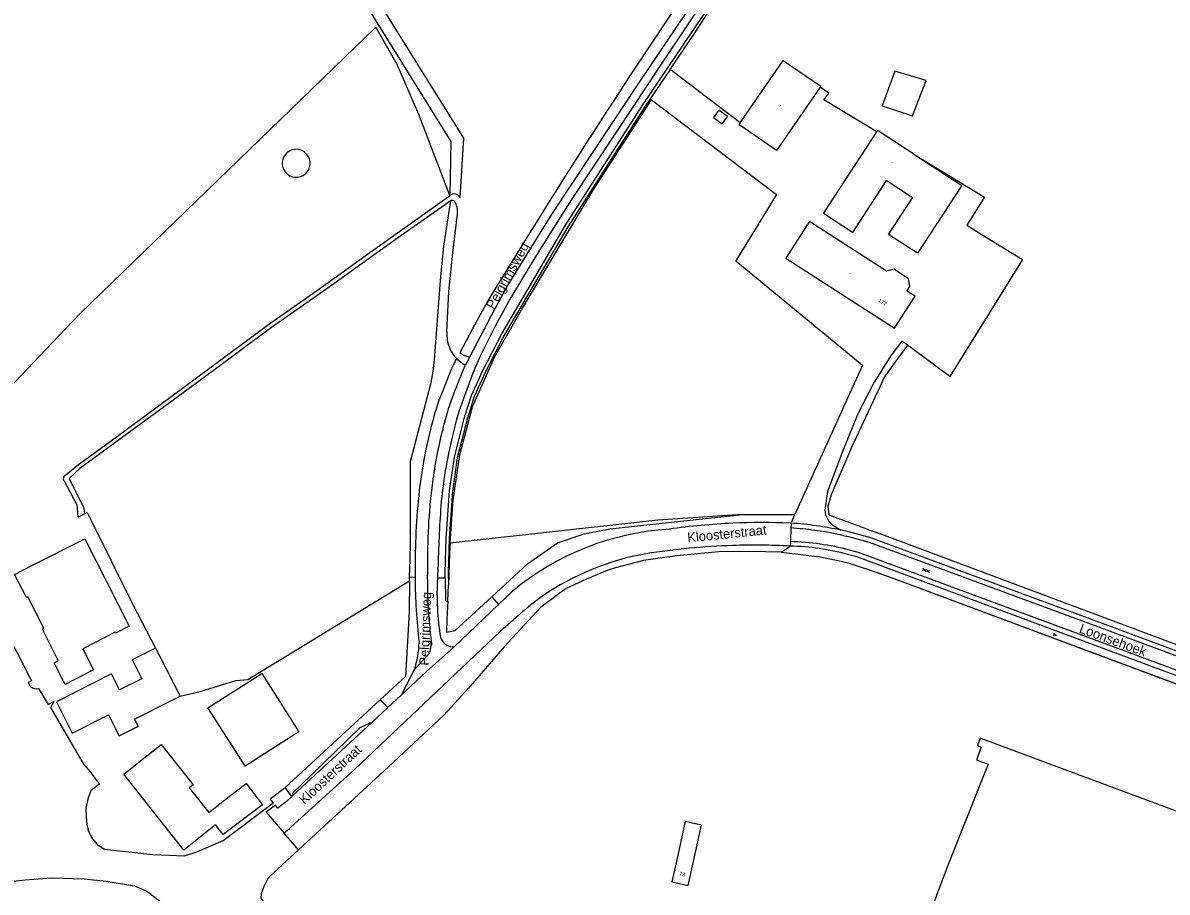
# Model space of a CAD drawing. Extents: x 134297 to 137000, y 403500 to 406000.
# Drawn here: x 134815.5 to 135112.9, y 404480.7 to 404706.5 of the extents above; entities that cross this region are included whole.
import ezdxf

# ---------------------------------------------------------------- set-up
doc = ezdxf.new("R2010")
doc.units = 0
for name, color, linetype in [('gg-afsc-hekwerk', 7, 'Continuous'), ('gg-anno-huisnummerreeks BGT', 7, 'Continuous'), ('gg-anno-openbare ruimte label', 7, 'Continuous'), ('gg-bbg-gedigitaliseerde bebouwing', 7, 'Continuous'), ('gg-knt-bronhoudergrens', 7, 'Continuous'), ('gg-knt-verharding', 7, 'Continuous'), ('gg-knt-verharding nz', 7, 'Continuous'), ('gg-kwrk-kunstwerk niveau 01', 7, 'Continuous'), ('gt-grn-vlakafsluiter', 7, 'Continuous'), ('gt-symb-gesloten verharding', 7, 'Continuous'), ('gt-symb-groenvak', 7, 'Continuous'), ('gx-grn-maaiveld', 7, 'Continuous'), ('kenmerkpunt-x pandkandidaat', 7, 'Continuous')]:
    doc.layers.add(name, color=color, linetype=linetype)

# ---------------------------------------------------------------- blocks, each defined once
blk = doc.blocks.new('gt0-GESVH1')
at = {"layer": 'gt-symb-gesloten verharding'}
for p, q in [((-0.99, -0.26), (0.01, 0.24)), ((0.01, -0.26), (-0.99, 0.24)), ((0.01, 0.24), (1.01, -0.26)), ((1.01, 0.24), (0.01, -0.26))]:
    blk.add_line(p, q, dxfattribs=at)
blk = doc.blocks.new('gt0-GRVAK')
at = {"layer": 'gt-symb-groenvak'}
for p, q in [((-0.11, 0.19), (-0.23, 0.24)), ((-0.18, 0.15), (0.09, 0.15)), ((-0.09, 0.21), (-0.16, 0.32)), ((-0.05, 0.21), (-0.05, 0.39)), ((0, 0.21), (0.06, 0.32)), ((0.01, 0.19), (0.13, 0.24)), ((0.26, -0.05), (0.2, 0.06)), ((0.3, -0.05), (0.3, 0.13)), ((0.35, -0.05), (0.41, 0.06)), ((-0.24, -0.23), (-0.36, -0.18)), ((-0.32, -0.26), (-0.05, -0.26)), ((-0.23, -0.21), (-0.29, -0.09)), ((-0.18, -0.2), (-0.18, -0.02)), ((-0.14, -0.21), (-0.07, -0.09)), ((-0.12, -0.23), (0, -0.18)), ((0.24, -0.07), (0.12, -0.02)), ((0.17, -0.11), (0.44, -0.11)), ((0.37, -0.07), (0.49, -0.02))]:
    blk.add_line(p, q, dxfattribs=at)

msp = doc.modelspace()

# ---------------------------------------------------------------- linework, layer by layer
at = {"layer": 'gg-afsc-hekwerk'}
for p, q in [((135122.11, 404542.43), (135037.34, 404574.08)), ((135122.11, 404542.43), (135037.34, 404574.08)), ((135012.56, 404568.97), (135021.94, 404567.88)), ((135012.56, 404568.97), (135021.94, 404567.88))]:
    msp.add_line(p, q, dxfattribs=at)
for points in [[(135064.59, 404651.64), (135075.27, 404645.01), (135056.39, 404614.65), (135045.46, 404622.75)], [(135064.59, 404651.64), (135075.27, 404645.01), (135056.39, 404614.65), (135045.46, 404622.75)], [(135045.46, 404622.75), (135039.52, 404614.74), (135030.86, 404596.22), (135025.61, 404583.91), (135024.7, 404580.95), (135024.97, 404578.72), (135037.34, 404574.08)], [(135045.46, 404622.75), (135039.52, 404614.74), (135030.86, 404596.22), (135025.61, 404583.91), (135024.7, 404580.95), (135024.97, 404578.72), (135037.34, 404574.08)], [(135028.58, 404566.5), (135027.75, 404566.7), (135021.94, 404567.88)], [(135028.58, 404566.5), (135027.75, 404566.7), (135021.94, 404567.88)], [(135142.46, 404524.59), (135041.29, 404562.36), (135035.66, 404564.37), (135030.02, 404566.16), (135028.58, 404566.5)], [(135135.38, 404527.23), (135041.29, 404562.36), (135035.66, 404564.37), (135030.02, 404566.16), (135028.58, 404566.5)]]:
    msp.add_lwpolyline(points, dxfattribs=at)
at = {"layer": 'gg-bbg-gedigitaliseerde bebouwing'}
for p, q in [((134987.67, 404499.05), (134985.28, 404488.31)), ((134985.28, 404488.31), (134984.19, 404483.39))]:
    msp.add_line(p, q, dxfattribs=at)
msp.add_lwpolyline([(134984.19, 404483.39), (134988.45, 404482.45), (134991.93, 404498.1), (134987.67, 404499.05)], dxfattribs=at)
at = {"layer": 'gg-knt-bronhoudergrens'}
msp.add_line((135045.46, 404622.75), (135043.97, 404623.86), dxfattribs=at)
for points in [[(135038.82, 404684.93), (135046.68, 404682.35), (135050.25, 404691.5), (135042.1, 404693.93), (135038.82, 404684.93)], [(135090.16, 404511.11), (135064.28, 404520.68), (135063.57, 404518.75), (135064.56, 404518.38), (135063.33, 404515.06), (135066.34, 404513.94), (135056.2, 404488.32), (135050.82, 404474.14)], [(135143.3, 404516.99), (135135.33, 404494.27), (135090.16, 404511.11)]]:
    msp.add_lwpolyline(points, dxfattribs=at)
at = {"layer": 'gg-knt-verharding'}
msp.add_line((135026.12, 404575.89), (135028.21, 404574.7), dxfattribs=at)
for points in [[(135043.97, 404623.86), (135041.18, 404620.14), (135036.74, 404613.13), (135032.6, 404605.12), (135028.87, 404596.06), (135024.66, 404584.74), (135023.94, 404579.94)], [(135123.82, 404540.3), (135123.58, 404540.29), (135096.09, 404550.5), (135035.91, 404572.74), (135032.11, 404573.75), (135030.16, 404574.25), (135028.21, 404574.7)], [(135142.9, 404526.67), (135032.23, 404567.77), (135029.87, 404568.43)]]:
    msp.add_lwpolyline(points, dxfattribs=at)
for centre, radius, start, end in [((135029.49, 404580.31), 5.56, 183.8429, 232.7198), ((135009.76, 404490.66), 86.04, 82.0085, 86.3918), ((135009.79, 404490.42), 86.26, 77.6738, 82.0524), ((135012.73, 404502.93), 67.71, 75.3382, 88.1133)]:
    msp.add_arc(centre, radius, start, end, dxfattribs=at)
at = {"layer": 'gg-knt-verharding nz'}
for points in [[(135338.24, 404460.8), (135277.14, 404482.92), (135242.75, 404495.33), (135175.85, 404519.54), (135095.8, 404549.24), (135035.57, 404571.53), (135031.77, 404572.55)], [(135337.05, 404457.55), (135292.12, 404473.78), (135254.86, 404487.29), (135219.48, 404500.07), (135174.55, 404516.34), (135091.7, 404547.08), (135032.68, 404568.9), (135030.32, 404569.56)]]:
    msp.add_lwpolyline(points, dxfattribs=at)
for centre, radius, start, end in [((135009.53, 404489.59), 85.88, 82.0692, 86.2648), ((135009.55, 404489.75), 85.73, 74.9784, 82.0667), ((135013.18, 404504.06), 67.71, 75.3387, 88.4566)]:
    msp.add_arc(centre, radius, start, end, dxfattribs=at)
at = {"layer": 'gg-kwrk-kunstwerk niveau 01'}
msp.add_lwpolyline([(134996.4, 404683.83), (134995.03, 404681.92), (134997.29, 404680.3), (134998.66, 404682.22), (134996.4, 404683.83)], dxfattribs=at)
at = {"layer": 'gt-grn-vlakafsluiter'}
for p, q in [((135015.17, 404576.53), (135016.12, 404578.8)), ((135015.17, 404576.53), (135015.13, 404575.29)), ((135015.13, 404575.29), (135015, 404571.74)), ((135012.56, 404568.97), (135014.96, 404570.6)), ((135015, 404571.74), (135014.96, 404570.6))]:
    msp.add_line(p, q, dxfattribs=at)
at = {"layer": 'gx-grn-maaiveld'}
for p, q in [((134983.71, 404694.36), (134990.4, 404704.26)), ((134983.71, 404694.36), (134978.58, 404686.77)), ((135001.95, 404680.57), (134983.71, 404694.36)), ((134978.58, 404686.77), (134978.91, 404686.51)), ((134931.69, 404619.76), (134930.49, 404617.52)), ((135002.5, 404578.8), (135016.12, 404578.8)), ((135014.92, 404576.54), (135015.17, 404576.53)), ((134916.03, 404561.52), (134916.04, 404562.49)), ((134917.48, 404562.42), (134916.04, 404562.49)), ((134925.31, 404562.22), (134923.25, 404562.24)), ((134925.93, 404556.31), (134926.1, 404560.52)), ((134939.16, 404555.45), (134942.76, 404558.89)), ((134939.16, 404555.45), (134927.62, 404544.41)), ((134937.39, 404557.41), (134939.16, 404555.45)), ((134927.62, 404544.41), (134927.11, 404544.43)), ((134917.36, 404538.62), (134921.33, 404542.84)), ((134917.26, 404538.43), (134913.82, 404531.85)), ((134917.26, 404538.43), (134917.36, 404538.62)), ((134910.36, 404528.64), (134913.82, 404531.85)), ((134883.72, 404507.84), (134908.36, 404530.61)), ((134910.36, 404528.64), (134906.27, 404524.85)), ((134908.36, 404530.61), (134910.36, 404528.64)), ((134906.27, 404524.85), (134885.81, 404505.86)), ((134885.47, 404505.54), (134883.72, 404507.84)), ((134885.81, 404505.86), (134885.47, 404505.54)), ((134887.2, 404491.72), (134883.47, 404496.04))]:
    msp.add_line(p, q, dxfattribs=at)
for points in [[(134662.77, 404873.92), (134709.41, 404898.07), (134755.06, 404920.31), (134782.12, 404909.74), (134808.83, 404884.68), (134864.49, 404823.03), (134885.72, 404801.9), (134901.93, 404787.59), (134901.68, 404731.86), (134901.68, 404718.1), (134901.82, 404717.58), (134902.63, 404714.52), (134926.76, 404675.71), (134926.49, 404661.64)], [(134925.31, 404562.22), (134925.3, 404563.66), (134925.55, 404572.58), (134926.42, 404584.92), (134927.66, 404593.7), (134930.33, 404604.04), (134932.11, 404609.68), (134935.03, 404616.23), (134939.98, 404625.76), (134956.53, 404653.95), (134976.62, 404685.25), (135000.68, 404720.83), (135008.69, 404730.74), (135012.1, 404734.14), (135013.26, 404735.38), (135013.68, 404735.7)], [(134996.1, 404726.76), (134990.86, 404727.18), (134960.47, 404724.36), (134930.11, 404732.01), (134904.81, 404732.25), (134904.82, 404718.74), (134905.6, 404715.81), (134930.02, 404676.54), (134929.09, 404661.13)], [(134929.66, 404607.83), (134932.57, 404615.57), (134934.44, 404620.02), (134938.37, 404627.79), (134941.92, 404634.27), (134945.43, 404640.19), (134949.87, 404647.48), (134958.2, 404660.61), (134969.84, 404678.14), (134981.85, 404696.3), (134993.58, 404713.92), (135000, 404722.81)], [(134931.69, 404619.76), (134935.47, 404627), (134938.19, 404632.11), (134941.43, 404638.04), (134952.89, 404656.66), (134975.56, 404690.83), (134993, 404716.76)], [(134990.4, 404704.26), (134993.37, 404708.85), (134994.28, 404710)], [(134926.49, 404661.64), (134918.43, 404682.69), (134912.76, 404695.65), (134907.25, 404705.4), (134830.39, 404631.03), (134828.42, 404628.96), (134824.84, 404625.21), (134792.1, 404590.87), (134791.04, 404589.67), (134805.39, 404560.94), (134805.75, 404560.45), (134807.94, 404553.97), (134813.79, 404543.35), (134817.77, 404535.62), (134816.94, 404535.14), (134817.55, 404534.01)], [(135001.95, 404680.57), (135013.14, 404696.77), (135022.9, 404690.03), (135022.75, 404689.82)], [(135022.75, 404689.82), (135011.36, 404673.34), (135001.86, 404679.9)], [(135037.44, 404678.2), (135023.68, 404686.52), (135024.98, 404688.28), (135022.75, 404689.82)], [(134978.58, 404686.77), (134977.27, 404684.83), (134957.19, 404653.55), (134940.65, 404625.39), (134935.73, 404615.89), (134932.83, 404609.41), (134931.07, 404603.83), (134928.41, 404593.55), (134927.19, 404584.84), (134926.32, 404572.54), (134926.07, 404563.65), (134926.1, 404560.52)], [(134926.61, 404571.38), (134927.36, 404582.64), (134929.08, 404594.28), (134932.38, 404606.72), (134938.2, 404619.82), (134945.07, 404631.98), (134964, 404663.47), (134978.91, 404686.51)], [(134978.91, 404686.51), (135011.42, 404661.94), (135000.78, 404644.69), (135033.72, 404617.57), (135016.12, 404578.8)], [(135001.95, 404680.57), (135001.61, 404680.07), (135001.86, 404679.9)], [(135047.36, 404672.18), (135059.5, 404664.29), (135048.02, 404646.64), (135040.52, 404651.51), (135046.75, 404661.09), (135039.91, 404665.54), (135031.16, 404652.08), (135023.63, 404656.97), (135037.44, 404678.2)], [(135047.36, 404672.18), (135037.64, 404678.51), (135037.44, 404678.2)], [(135047.36, 404672.18), (135065.47, 404661.22), (135060.84, 404653.95), (135064.59, 404651.64)], [(134826.61, 404589.01), (134829.67, 404591.54), (134840.51, 404599.4), (134858.62, 404612.81), (134869.98, 404621.22), (134879.14, 404627.99), (134892.09, 404637.04), (134905.07, 404646.41), (134924.62, 404660.3), (134926.49, 404661.64)], [(134926.53, 404660.2), (134925.33, 404659.35), (134912.25, 404650.11), (134895.1, 404637.88), (134880.12, 404627.34), (134862.05, 404613.92), (134830.32, 404590.71), (134827.55, 404588.1), (134828.19, 404586.84), (134831.24, 404580.85), (134831.32, 404580.49), (134831.66, 404578.96)], [(134916.04, 404562.49), (134916.04, 404562.58), (134916.16, 404567.03), (134916.29, 404571.53), (134916.28, 404592.57), (134921.6, 404613.05), (134922.14, 404615.97), (134922.49, 404618.94), (134924.06, 404639.6), (134924.96, 404648.47), (134926.77, 404660.34)], [(134925.73, 404626.24), (134926.21, 404636.69), (134927.27, 404646.74), (134928.5, 404656.82)], [(135019.25, 404653.9), (135013.77, 404645.39), (135042.03, 404627.19), (135047.37, 404635.48), (135045.25, 404636.85), (135046.06, 404638.11), (135045.67, 404640.04), (135041.87, 404642.49), (135039.99, 404642.02), (135019.93, 404654.94), (135019.25, 404653.9)], [(134936.34, 404634.26), (134932.38, 404627.03), (134929.1, 404620.81)], [(134928.18, 404619.37), (134927.33, 404617.49), (134926.86, 404616.45), (134925.05, 404611.9)], [(134928.21, 404611.92), (134930.02, 404616.47), (134930.49, 404617.52)], [(134831.66, 404578.96), (134830.61, 404578.44), (134829.93, 404578.1), (134829.7, 404580.43), (134829.62, 404581.21), (134826.34, 404587.44)], [(134831.66, 404578.96), (134832.28, 404579.27), (134833.56, 404576.75), (134838.59, 404566.62), (134844.16, 404555.27), (134850, 404544.07)], [(135002.5, 404578.8), (134980.53, 404577.32), (134926.61, 404571.38)], [(134937.39, 404557.41), (134946.67, 404565.97), (134954.48, 404571.4), (134961.36, 404573.78), (134968.1, 404575.1), (135002.5, 404578.8)], [(134843.14, 404549.78), (134839.63, 404547.99), (134839.52, 404548.2), (134831.12, 404543.93), (134833.93, 404538.4), (134826.56, 404534.64), (134823.67, 404540.3), (134824.74, 404540.83), (134820.6, 404549.02), (134820.98, 404549.22), (134816.84, 404557.38), (134816.47, 404557.2), (134813.4, 404563.23), (134817.85, 404565.5), (134831.62, 404572.5), (134843.14, 404549.78)], [(134926.61, 404571.38), (134926.43, 404568.75), (134926.1, 404560.52)], [(135012.56, 404568.97), (135004.47, 404569.14), (134996.3, 404569.05), (134985.49, 404568.03), (134976.81, 404566.88), (134969.51, 404564.9), (134967.4, 404564.25), (134961.96, 404561.95), (134956.69, 404559.57), (134950.16, 404554.7), (134940.6, 404544.42), (134931.31, 404533.7), (134924.94, 404526.67), (134910.59, 404513.27), (134887.2, 404491.72)], [(134856.38, 404531.57), (134861.65, 404532.84), (134870.91, 404535.65), (134873.97, 404535.94), (134916.03, 404561.52)], [(134916.03, 404561.52), (134915.95, 404553.48), (134914.99, 404536.74), (134908.36, 404530.61)], [(134925.31, 404562.22), (134925.37, 404556.44), (134925.54, 404556.27), (134925.76, 404556.27), (134925.93, 404556.31)], [(134925.93, 404556.31), (134925.74, 404551.6), (134925.64, 404548.24), (134927.89, 404548.64), (134937.39, 404557.41)], [(134944.31, 404552.54), (134939.57, 404548.38), (134901.59, 404512.42), (134885.13, 404497.53)], [(134850, 404544.07), (134843.96, 404541), (134844.96, 404539.03), (134846.43, 404536.11), (134840.67, 404533.21), (134838.55, 404537.43), (134828.69, 404532.42), (134824.23, 404530.15), (134828.38, 404521.99), (134837.82, 404526.73), (134840.58, 404521.3), (134845.04, 404523.56), (134845.49, 404523.79), (134844.58, 404525.58), (134854.2, 404530.46), (134856.38, 404531.57)], [(134850, 404544.07), (134851.03, 404542.11), (134854.58, 404535.13), (134856.38, 404531.57)], [(134913.82, 404531.85), (134920.44, 404538), (134927.62, 404544.41)], [(134873.3, 404513.43), (134870.61, 404517.65), (134863.64, 404528.58), (134877.59, 404537.48), (134884.58, 404526.55), (134887.27, 404522.34), (134873.3, 404513.43)], [(134819.6, 404533.56), (134822.07, 404529.4), (134823.59, 404530.22), (134822.72, 404528.66), (134831.29, 404513.9), (134833.11, 404511.83), (134834.75, 404509.64), (134835.41, 404508.84), (134833.23, 404507.03), (134832.47, 404505.22), (134831.87, 404502.53), (134831.96, 404500.32), (134832.13, 404498.33), (134832.32, 404497.54), (134832.51, 404496.72), (134833.34, 404494.88), (134834.87, 404493.09), (134836.72, 404491.86), (134849.34, 404490.43), (134857.56, 404490.1), (134860.76, 404491.19), (134867.62, 404494.09), (134880.52, 404503.78), (134880.66, 404503.89), (134879.83, 404504.89), (134883.72, 404507.84)], [(134906.27, 404524.85), (134903.12, 404523.4), (134890.44, 404511.06), (134885.59, 404506.39), (134885.81, 404505.86)], [(134859.77, 404508.59), (134858.74, 404507.77), (134863.82, 404501.34), (134869.58, 404505.89), (134873.55, 404508.93), (134877.82, 404503.37), (134868.04, 404496.01), (134867.59, 404495.67), (134865.62, 404498.17), (134857.35, 404491.62), (134841.76, 404511.34), (134845.68, 404514.44), (134851.5, 404519.04), (134859.77, 404508.59)], [(134885.47, 404505.54), (134884.05, 404504.22), (134881.78, 404502.54), (134881.16, 404503.28), (134878.8, 404501.44), (134883.47, 404496.04)], [(134887.2, 404491.72), (134881.78, 404486.73), (134879.27, 404484.31), (134878.11, 404482.13), (134877.44, 404480.27), (134877.41, 404479.25), (134878.9, 404476.68), (134880.51, 404474.64), (134881.17, 404473.79), (134884.02, 404470.48)], [(134810.46, 404483.31), (134816.12, 404483.88), (134822.92, 404484.41), (134831.5, 404484.16), (134837.21, 404483.58), (134844.58, 404482.32), (134847.54, 404481.02), (134848.61, 404480.35), (134859.61, 404471.7), (134864.34, 404469), (134873.97, 404460.75), (134873.95, 404460.65), (134873.4, 404458.44), (134875.31, 404456.78), (134876.43, 404455.9), (134878.44, 404454.18), (134881.22, 404451.65)]]:
    msp.add_lwpolyline(points, dxfattribs=at)
for centre, radius, start, end in [((136639.96, 403599.17), 1993.42, 145.5521, 148.71794), ((134886.58, 404670.05), 3.65, 120.1663, 299.2203), ((134886.53, 404670.02), 3.65, 300.1663, 119.2203), ((134927.6, 404660.4), 1.66, 26.0513, 131.8896), ((134927.09, 404659.53), 0.872, 111.647, 129.8529), ((134927.12, 404659.48), 0.924, 48.5889, 112.2738), ((134922.7, 404657.25), 5.82, 355.7498, 30.2519), ((134934.67, 404625.56), 8.97, 175.6854, 220.9008), ((134932.19, 404624.69), 4.96, 231.4225, 252.2445), ((134934.95, 404625.81), 9.34, 220.9506, 223.5967), ((134934.71, 404625.6), 9.02, 223.6996, 234.6428), ((134934.48, 404625.27), 8.62, 234.5795, 239.036), ((134929.52, 404616.76), 1.24, 37.8643, 64.5976), ((134932.18, 404624.68), 4.95, 252.2643, 264.3383), ((134982.33, 404587.28), 62.34, 156.7422, 164.2286), ((134985.49, 404587.31), 62.34, 156.7422, 164.2286), ((134989.88, 404585.83), 64.12, 159.9269, 167.9759), ((135042.63, 404570.48), 124.94, 164.3288, 172.7118), ((135045.79, 404570.5), 124.94, 164.3287, 171.1682), ((135045.78, 404570.17), 122.11, 166.2547, 174.8974), ((134826.99, 404588.14), 0.951, 113.4834, 227.3084), ((135048.42, 404570.13), 127.6, 171.1839, 172.6955), ((135079.96, 404566.55), 162.47, 173.0083, 180.5758), ((135083.12, 404566.57), 162.47, 173.0083, 180.5758), ((135308.19, 404555.23), 384.9, 176.1567, 178.6017), ((135007.64, 404404.98), 171.71, 92.5486, 98.071), ((135007.67, 404405.01), 171.68, 87.5799, 92.5584), ((134987.88, 404504.29), 70.83, 93.5193, 129.5729), ((135005.82, 404388.5), 182.32, 91.8306, 98.9483), ((135005.84, 404388.44), 182.39, 87.1322, 91.8339), ((134989.53, 404500.58), 69.09, 100.0577, 124.3636), ((135058.63, 404562.71), 141.15, 179.1033, 180.1149), ((135065.45, 404562.69), 144.81, 179.1109, 186.7791), ((135002.38, 404558.2), 79.24, 175.3456, 177.0741), ((135062.13, 404562.66), 144.65, 180.0923, 186.7822), ((134999.32, 404558.4), 76.17, 177.1108, 188.7269), ((134996.57, 404494.83), 77.85, 126.2553, 132.1637), ((134927.55, 404548.16), 3.76, 200.5281, 263.2283), ((134893.58, 404546.21), 24.93, 341.8295, 358.5493), ((134910.68, 404545.49), 10.97, 346.0516, 0.5842), ((134819.09, 404536.16), 2.65, 234.3078, 280.9723), ((134819.19, 404569.59), 97.67, 311.1525, 312.4637)]:
    msp.add_arc(centre, radius, start, end, dxfattribs=at)

# ---------------------------------------------------------------- block references
at = {"layer": 'gt-symb-gesloten verharding', "rotation": -20.428617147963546}
msp.add_blockref('gt0-GESVH1', (135050.27, 404564.26), dxfattribs=at)
at = {"layer": 'gt-symb-groenvak'}
msp.add_blockref('gt0-GRVAK', (135083.62, 404547.58), dxfattribs=at)

# ---------------------------------------------------------------- texts
at = {"layer": 'gg-anno-huisnummerreeks BGT'}
for s, rotation, p in [('177', 327.2, (135037.73, 404634.12)), ('78', 347.5, (134986, 404485.04))]:
    msp.add_text(s, height=1, rotation=rotation, dxfattribs=at).set_placement(p)
at = {"layer": 'gg-anno-openbare ruimte label'}
for s, rotation, p in [('Pelgrimsweg', 61.3, (134937.96, 404631.86)), ('Kloosterstraat', 5.8, (134988.34, 404571.53)), ('Pelgrimsweg', 88, (134921.01, 404539.51)), ('Loonsehoek', 339.8, (135089.84, 404548.19)), ('Kloosterstraat', 43.1, (134888.71, 404503.3))]:
    msp.add_text(s, height=2.5, rotation=rotation, dxfattribs=at).set_placement(p)
at = {"layer": 'kenmerkpunt-x pandkandidaat'}
for p in [(135011.88, 404684.95), (135041.19, 404670.11), (135030.2, 404641.23)]:
    msp.add_text('PNDK', height=0.2, dxfattribs=at).set_placement(p)

doc.saveas('drawing.dxf')
